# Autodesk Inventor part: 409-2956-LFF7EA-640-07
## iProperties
Shininess: 64.0
Angle Display Precision: 2
Document Length Units: 11272
Document Angle Units: 11279
Document Time Units: 11290
Document Mass Units: 11286
Document Length Units Precision: 3
Document Angle Units Precision: 2
Compacted: True
Created: 2002-04
Part Number: 409-2956-LFF7EA-640-07
Description: PSL MOUNT ANGLE
Document SubType Name: Modeling
Designer: S. Boerckel
Mass: 457.732 g
Surface Area: 261.703 cm^2
Volume: 58.2356 cm^3
Density: 7.86 g/cm^3
Cost Center: 2 x 2 x 3/16 HR ANGLE
User Status: SAW/PUNCH
Material: ASTM A36 STEEL
Engineer: S. Boerckel
Density: 0.0
Volumn: 0.0
Area: 0.0
PropertySet Name: Model Information
Control State: 0
Master: False
Checked Out: False
SMR: =<COST CENTER> <MATERIAL>
LGTH: 5.000 in
Author: S. Boerckel
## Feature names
1. Extrusion1
2. Hole1
